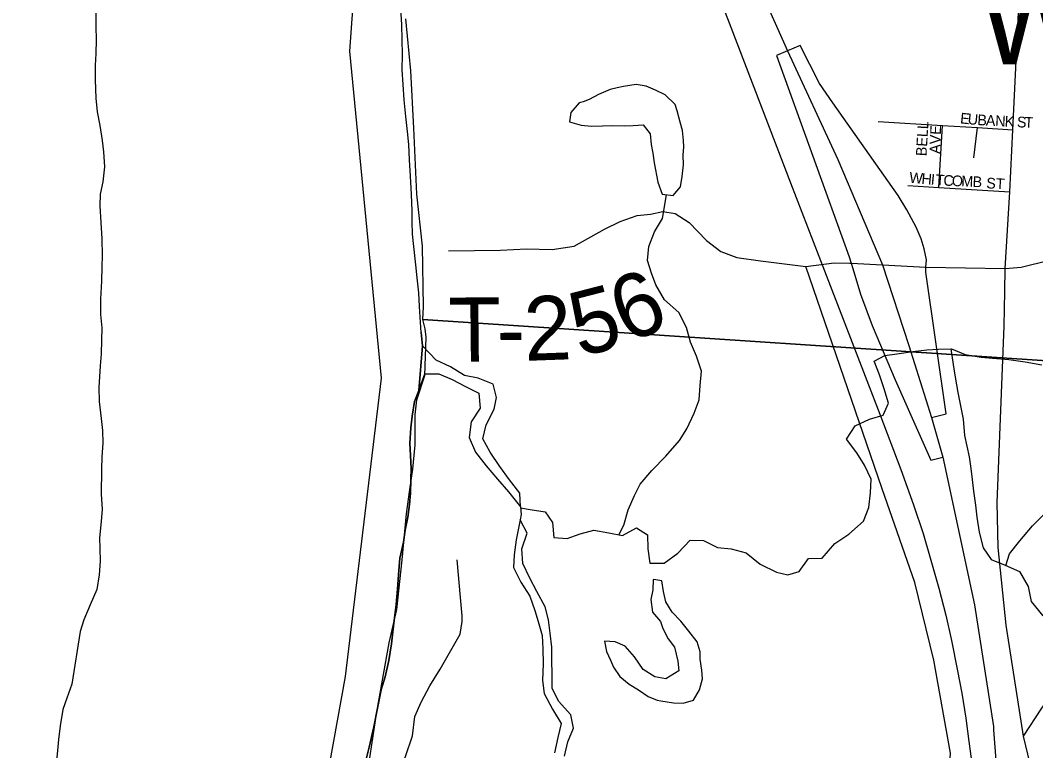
# Model space of a CAD drawing. Extents: x 1624196 to 2029251, y 146837 to 440034.
# Drawn here: x 1861259 to 1866006, y 263439 to 266854 of the extents above; entities that cross this region are included whole.
import ezdxf

# ---------------------------------------------------------------- set-up
doc = ezdxf.new("R2010")
doc.units = 0
for name, color, linetype in [('GM_X_County', 7, 'Continuous'), ('GM_X_County_Road', 7, 'Continuous'), ('GM_X_Interchange_Ramps', 7, 'Continuous'), ('GM_X_Major_River', 7, 'Continuous'), ('GM_X_Minor_Lake', 7, 'Continuous'), ('GM_X_Minor_River', 7, 'Continuous'), ('GM_X_Rail_Line', 7, 'Continuous'), ('GM_X_Section', 7, 'Continuous'), ('GM_X_Township', 7, 'Continuous'), ('GM_X_Township_Road', 7, 'Continuous'), ('GM_X_Township_Road_Text', 7, 'Continuous'), ('GM_X_Township_Subdivision', 7, 'Continuous'), ('GM_X_Township_Subdivision_Text', 7, 'Continuous'), ('GM_X_Unincorporated_Text', 7, 'Continuous'), ('GM_X_US_Route', 7, 'Continuous')]:
    doc.layers.add(name, color=color, linetype=linetype)

msp = doc.modelspace()

# ---------------------------------------------------------------- linework, layer by layer
at = {"layer": 'GM_X_County'}
msp.add_lwpolyline([(1861843.4, 259153), (1862035.4, 260236.2), (1862367.4, 261505.6), (1862779.4, 263786.1), (1862947.5, 265181.7), (1862799.4, 266709.4), (1862843.4, 267316), (1862763.4, 267754.5), (1862639.3, 268445.3), (1862487.3, 269170.1), (1861981.2, 270988.1)], dxfattribs=at)
at = {"layer": 'GM_X_County_Road'}
for points in [[(1865863.4, 265693.9), (1865885.2, 266051.4), (1865900.3, 266342.6), (1865929.5, 266955.7), (1865926.1, 266996.5), (1865898.2, 267331), (1865896.1, 267346.9), (1865864.8, 267587.2), (1865804.2, 267809), (1865652.5, 268167.6), (1865418.2, 268553.8), (1865101.1, 268983.1), (1864229.9, 270238.6), (1863859.8, 270764.2), (1863654.2, 271050.8), (1863523.3, 271223.8), (1863423.3, 271348.3)], [(1865950, 263507.3), (1866034.8, 263637.4), (1866288, 263981.4), (1866419, 264182.9), (1866423.7, 264340), (1866465.6, 265074.8), (1866481.8, 265246.8), (1866507.6, 265556.1), (1866547.4, 266035.5), (1866595.6, 266755), (1866622.7, 266795.6)], [(1865863.4, 265693.9), (1865938.4, 265700.3), (1866071.1, 265732), (1866071.3, 265732.2)], [(1864931.8, 265703.2), (1865063.4, 265720.6), (1865138, 265719.1)], [(1865418.7, 262834.6), (1865578.9, 263041.4), (1865602.6, 263332.1), (1865608.2, 263428.2), (1865530.6, 263862.9), (1865441.2, 264225.9), (1865288.3, 264663.7), (1864931.8, 265703.2)], [(1865138, 265719.1), (1865144, 265719), (1865289.4, 265711.1), (1865493.1, 265700), (1865863.4, 265693.9)], [(1865861.6, 265586.7), (1865863.4, 265693.9)], [(1867016.2, 259449.3), (1866680.5, 260648), (1866378.1, 261727.9), (1865950, 263507.3), (1865868, 264025.5), (1865831.5, 264390), (1865827, 264599.6), (1865858.9, 265423.9), (1865861.6, 265586.7)]]:
    msp.add_lwpolyline(points, dxfattribs=at)
at = {"layer": 'GM_X_Interchange_Ramps'}
for points in [[(1865493.1, 265700), (1865496, 265735), (1865484.2, 265786), (1865470.9, 265832.2), (1865447.8, 265886.8), (1865404, 265968.5), (1865362.9, 266035.5), (1865057.9, 266468.9), (1864996.3, 266558.4), (1864905.3, 266736.4), (1864846, 266712.1)], [(1864846, 266712.1), (1864794.2, 266689.2), (1865133.9, 265747.6), (1865144, 265719)], [(1865144, 265719), (1865150.7, 265693), (1865187.7, 265574.1), (1865241.6, 265426.8), (1865349.6, 265173.5), (1865466.1, 264910), (1865516.5, 264797.1), (1865572, 264811.4)], [(1865519, 264997.2), (1865587.5, 265014.8), (1865493.5, 265677.2), (1865493.1, 265700)]]:
    msp.add_lwpolyline(points, dxfattribs=at)
at = {"layer": 'GM_X_Major_River'}
for p, q in [((1863138.6, 265331.8), (1863132.9, 265393.9)), ((1863138.6, 265331.8), (1863121.5, 265123.5)), ((1863121.5, 265123.5), (1863138.6, 265331.8))]:
    msp.add_line(p, q, dxfattribs=at)
for points in [[(1861612.7, 266890.6), (1861612.4, 266824.5), (1861614, 266762.4), (1861611.7, 266698.3), (1861609.4, 266642.3), (1861609.1, 266576.2), (1861612.7, 266490), (1861618.4, 266425.9), (1861630, 266361.8), (1861641.7, 266291.6), (1861647.4, 266239.5), (1861653.1, 266169.4), (1861644.7, 266099.3), (1861632.4, 266041.3), (1861630.2, 265987.2), (1861635.8, 265909.1), (1861639.4, 265833), (1861641, 265754.9), (1861640.7, 265700.8), (1861638.4, 265634.7), (1861634, 265550.6), (1861633.6, 265478.5), (1861639.3, 265416.4), (1861639, 265358.3), (1861636.7, 265294.2), (1861632.4, 265238.2), (1861625.9, 265138), (1861627.6, 265072), (1861637.2, 264991.8), (1861642.9, 264935.7), (1861644.6, 264877.6), (1861640.3, 264813.5), (1861638, 264755.5), (1861637.5, 264639.3), (1861641.1, 264569.2), (1861636.8, 264511.1), (1861628.4, 264435), (1861630.2, 264385), (1861631.9, 264324.9), (1861627.6, 264260.8), (1861617.2, 264192.7), (1861584.9, 264120.8), (1861556.5, 264050.8), (1861538.3, 263996.8), (1861500.5, 263750.6)], [(1863132.9, 265393.9), (1863129.2, 265466), (1863125.5, 265516.1), (1863121.8, 265580.2), (1863114.2, 265650.3), (1863108.5, 265710.4), (1863098.9, 265796.6), (1863093.2, 265854.7), (1863091.5, 265912.8), (1863091.7, 265962.8), (1863088.1, 266039), (1863082.5, 266125.1), (1863078.9, 266201.2), (1863075.3, 266273.4), (1863069.6, 266333.5), (1863061.9, 266403.6), (1863054.3, 266481.8), (1863048.7, 266553.9), (1863045, 266622), (1863045.4, 266694.1), (1863043.7, 266762.2), (1863042.1, 266834.3), (1863038.5, 266908.4)], [(1863132.9, 265393.9), (1863138.6, 265331.8)], [(1862877.1, 263406.1), (1862889.3, 263456.2), (1862911.8, 263550.2), (1862928.2, 263638.2), (1862946.6, 263724.3), (1862964.9, 263784.3), (1862981.3, 263860.3), (1862993.7, 263938.4), (1862999.9, 263994.4), (1863008.3, 264060.5), (1863016.6, 264122.6), (1863022.9, 264194.6), (1863027.3, 264260.7), (1863033.7, 264338.8), (1863050, 264414.8), (1863058.3, 264470.9), (1863070.6, 264530.9), (1863078.9, 264591), (1863083.2, 264643), (1863085.5, 264707.1), (1863085.7, 264759.2), (1863084, 264819.2), (1863080.3, 264877.3), (1863084.7, 264949.4), (1863091, 265003.5), (1863101.3, 265071.5), (1863121.5, 265123.5)], [(1863121.5, 265123.5), (1863101.3, 265071.5), (1863091, 265003.5), (1863084.7, 264949.4), (1863080.3, 264877.3), (1863084, 264819.2), (1863085.7, 264759.2), (1863085.5, 264707.1), (1863083.2, 264643), (1863078.9, 264591), (1863070.6, 264530.9), (1863058.3, 264470.9), (1863050, 264414.8), (1863033.7, 264338.8), (1863027.3, 264260.7), (1863022.9, 264194.6), (1863016.6, 264122.6), (1863008.3, 264060.5), (1862999.9, 263994.4), (1862993.7, 263938.4), (1862981.3, 263860.3), (1862964.9, 263784.3), (1862946.6, 263724.3), (1862928.2, 263638.2), (1862911.8, 263550.2), (1862889.3, 263456.2), (1862877.1, 263406.1)], [(1861500.5, 263750.6), (1861476.2, 263684.4), (1861457.9, 263632.3), (1861445.6, 263556.1), (1861437.3, 263491.9), (1861431, 263423.7), (1861422.7, 263357.4), (1861412.4, 263279.2), (1861404.1, 263221), (1861399.8, 263138.7), (1861395.5, 263070.5), (1861391.2, 263008.2), (1861382.9, 262940), (1861378.7, 262883.8), (1861372.4, 262815.5), (1861363.9, 262715.2), (1861353.6, 262643), (1861341.3, 262584.8), (1861329.1, 262520.6), (1861314.8, 262456.5), (1861296.4, 262388.3), (1861284.2, 262326.1), (1861267.9, 262255.9), (1861258.8, 262210.4)], [(1861500.5, 263750.6), (1861476.2, 263684.4), (1861457.9, 263632.3), (1861445.6, 263556.1), (1861437.3, 263491.9), (1861431, 263423.7)]]:
    msp.add_lwpolyline(points, dxfattribs=at)
at = {"layer": 'GM_X_Minor_Lake'}
for points in [[(1864259.5, 266040.7), (1864311.4, 266034.3), (1864345.6, 266076.2), (1864353.9, 266124.1), (1864360.3, 266178.2), (1864358.6, 266224.2), (1864360.8, 266262.2), (1864359, 266292.3), (1864355.3, 266338.3), (1864343.6, 266378.4), (1864329.9, 266430.6), (1864320.1, 266460.7), (1864274.4, 266505), (1864228.6, 266527.3), (1864184.7, 266545.6), (1864138.8, 266553.9), (1864078.8, 266544.2), (1864048.8, 266538.4), (1864016.8, 266530.6), (1863962.7, 266507), (1863918.6, 266483.2), (1863890.5, 266473.6)], [(1863890.5, 266473.6), (1863872.5, 266467.5), (1863832.3, 266423.7), (1863826, 266379.7), (1863881.8, 266363.3), (1863929.8, 266359), (1863981.7, 266360.7), (1864029.7, 266362.4), (1864081.7, 266360.1), (1864123.6, 266361.8), (1864171.6, 266365.5), (1864203.3, 266323.3), (1864209, 266273.2), (1864216.7, 266233.1), (1864222.5, 266187), (1864239.9, 266096.8), (1864259.5, 266040.7)], [(1864230.1, 264237.5), (1864218.2, 264239.4), (1864215.9, 264191.4), (1864207.6, 264145.4), (1864215.2, 264087.3), (1864252.9, 264043), (1864262.7, 264010.9), (1864288.4, 263962.7), (1864318.1, 263922.5), (1864333.7, 263858.3), (1864337.4, 263812.3), (1864277.2, 263774.6), (1864225.3, 263785), (1864171.6, 263819.3), (1864130, 263877.6), (1864086.3, 263928), (1864040.5, 263948.3), (1863990.6, 263950.6), (1864000.2, 263902.5), (1864018, 263862.3), (1864031.8, 263830.2), (1864061.5, 263786), (1864105.2, 263749.7), (1864149, 263723.4), (1864194.8, 263693.1), (1864236.6, 263674.8), (1864253.8, 263672.6)], [(1864253.8, 263672.6), (1864312.5, 263662.3), (1864358.4, 263662), (1864406.5, 263675.7), (1864434.8, 263723.6), (1864449.1, 263775.5), (1864445.3, 263815.6), (1864437.7, 263867.7), (1864437.9, 263901.7), (1864424.2, 263947.8), (1864384.5, 263998.1), (1864346.8, 264044.4), (1864307.1, 264086.7), (1864277.5, 264134.9), (1864265.8, 264183), (1864258.1, 264233.1), (1864230.1, 264237.5)]]:
    msp.add_lwpolyline(points, dxfattribs=at)
at = {"layer": 'GM_X_Minor_River'}
msp.add_line((1863138.6, 265331.8), (1863121.5, 265123.5), dxfattribs=at)
for points in [[(1864058, 264448.5), (1864080.1, 264493.4), (1864100.7, 264565.3), (1864131.2, 264633.1), (1864157.6, 264685), (1864212.1, 264748.6), (1864276.5, 264816.2), (1864341.1, 264889.8), (1864375.5, 264943.5), (1864410, 265017.3), (1864432.5, 265079.2), (1864437, 265147.3), (1864443.6, 265213.3), (1864420.1, 265283.6), (1864392.7, 265349.8), (1864373.2, 265418.1), (1864337.8, 265488.4), (1864270.3, 265547), (1864230.9, 265617.4), (1864209.3, 265671.6), (1864191.8, 265731.8), (1864198.3, 265795.9), (1864224.8, 265865.7), (1864261.3, 265927.5), (1864279.5, 266038.2)], [(1863121.5, 265123.5), (1863150.4, 265201.4), (1863216.3, 265200.9), (1863278.1, 265174.4), (1863339.8, 265141.9), (1863403.5, 265111.4), (1863408.9, 265041.2), (1863366.5, 264977.5), (1863357.9, 264903.5), (1863387.3, 264835.2), (1863436.8, 264770.7), (1863490.2, 264708.2), (1863541.8, 264649.8), (1863597.2, 264579.2), (1863593.7, 264643.3), (1863546.2, 264705.8), (1863500.7, 264768.2), (1863455.3, 264834.6), (1863421.8, 264897), (1863436.3, 264962.9), (1863474.8, 265036.7), (1863485.3, 265090.7), (1863469.8, 265152.9), (1863400, 265181.5), (1863336.2, 265194), (1863270.5, 265234.5), (1863202.8, 265265.1), (1863138.6, 265331.8)], [(1863597.6, 264575), (1863643, 264566.9), (1863712.9, 264556.3), (1863746.5, 264506), (1863753.9, 264435.9), (1863815.8, 264431.4), (1863876, 264452.9), (1863940.1, 264470.4), (1864009.9, 264457.9), (1864073.8, 264445.4), (1864140, 264480.9), (1864191.7, 264448.4), (1864193.2, 264382.3), (1864202.7, 264316.2), (1864268.6, 264315.7), (1864332.9, 264363.2), (1864391.4, 264422.8), (1864453.3, 264422.4), (1864519, 264389.8), (1864582.9, 264383.3), (1864652.7, 264364.7), (1864718.3, 264312.1), (1864793.9, 264273.5), (1864847.8, 264261.1), (1864899.8, 264276.7), (1864944.3, 264338.4), (1865008.3, 264339.9), (1865066.8, 264407.5), (1865133, 264451), (1865201.5, 264512.6), (1865226, 264576.5), (1865234.5, 264644.5), (1865237, 264708.5), (1865205.6, 264774.8), (1865170, 264831.2), (1865122.6, 264895.6), (1865163, 264957.4), (1865229.2, 264988.9), (1865293.3, 265008.4), (1865317.8, 265064.3), (1865298.3, 265130.5), (1865276.8, 265196.7), (1865251.4, 265261), (1865301.5, 265286.6), (1865357.5, 265294.2), (1865431.6, 265305.6), (1865497.6, 265313.1), (1865551.6, 265316.7), (1865613.5, 265318.2), (1865677.3, 265291.7), (1865751.1, 265279.1), (1865805.1, 265274.7), (1865881, 265268.1), (1865956.8, 265257.5), (1866034.7, 265242.8)], [(1865609.4, 265318.1), (1865621, 265244.1), (1865630.5, 265186), (1865641.9, 265113.8), (1865653.5, 265059.6), (1865666.9, 264989.5), (1865674.3, 264913.3), (1865683.9, 264863.2), (1865695.5, 264813), (1865703.1, 264758.9), (1865708.7, 264706.8), (1865716.2, 264652.7), (1865725.7, 264586.5), (1865731.3, 264530.4), (1865742.7, 264460.3), (1865760.1, 264388), (1865797.7, 264333.7), (1865863.4, 264307.2), (1865931.1, 264276.6), (1865970.5, 264206.2), (1865986, 264136), (1866039.4, 264069.5)], [(1863597.2, 264579.2), (1863600.8, 264543.6), (1863596.7, 264519.2)], [(1865866.9, 264305.6), (1865883.8, 264359), (1865932.2, 264420.7), (1865990.8, 264490.4), (1866051.2, 264549.9)], [(1863596.7, 264519.2), (1863578, 264425.2), (1863567.4, 264355.2), (1863564.9, 264295.2), (1863598.4, 264226.9), (1863641.8, 264162.4), (1863665.3, 264094.2), (1863680.9, 264044), (1863698.3, 263977.8), (1863701.9, 263915.7), (1863703.3, 263845.6), (1863700.7, 263767.5), (1863708.2, 263707.4), (1863747.6, 263633), (1863787, 263566.6), (1863772.5, 263500.7), (1863756, 263428.7)], [(1863803.8, 263414.3), (1863818.3, 263480.3), (1863844.8, 263544.2), (1863833.3, 263606.3), (1863775.9, 263670.8), (1863746.4, 263731.1), (1863744.9, 263799.2), (1863743.4, 263859.3), (1863743.9, 263923.4), (1863736.4, 263989.5), (1863728.9, 264051.6), (1863713.4, 264111.8), (1863674, 264184.2), (1863640.5, 264246.5), (1863609.1, 264314.9), (1863603.6, 264383), (1863628.2, 264456.9), (1863596.7, 264519.2)]]:
    msp.add_lwpolyline(points, dxfattribs=at)
at = {"layer": 'GM_X_Rail_Line'}
msp.add_lwpolyline([(1864240.5, 267704.5), (1864580.6, 266822.7), (1864859.5, 266094.9), (1865045.7, 265614.5), (1865277, 265012.4), (1865375.4, 264753.7), (1865435.8, 264588.4), (1865480.1, 264454.6), (1865513.2, 264340.2), (1865554.3, 264199.1), (1865585.7, 264072.6), (1865613.1, 263954.1), (1865640.5, 263813.1), (1865661.5, 263707.5), (1865679.2, 263591.4), (1865694.5, 263482.6), (1865705, 263402.8)], dxfattribs=at)
at = {"layer": 'GM_X_Section'}
for points in [[(1866483.9, 265233.4), (1863140.4, 265454.9), (1863144.6, 265514.9), (1863139.6, 265798.9), (1863112.4, 266041), (1863099.5, 266349.1), (1863084.4, 266617.2), (1863061.2, 266861.3)], [(1862893.4, 263405.5), (1862926.1, 263621.5), (1862983.2, 263943.3), (1863019.8, 264099.2), (1863044.6, 264331.1), (1863065.3, 264547.1), (1863079.7, 264661), (1863094, 264755), (1863104.4, 264868.9), (1863104.9, 265009), (1863113.1, 265078.9), (1863149.5, 265192.9), (1863156.1, 265372.8), (1863152.3, 265410.9), (1863140.4, 265454.9), (1866483.9, 265233.4)]]:
    msp.add_lwpolyline(points, dxfattribs=at)
at = {"layer": 'GM_X_Township'}
msp.add_lwpolyline([(1861843.4, 259153), (1862035.4, 260236.2), (1862367.4, 261505.6), (1862779.4, 263786.1), (1862947.5, 265181.7), (1862799.4, 266709.4), (1862843.4, 267316), (1862763.4, 267754.5), (1862639.3, 268445.3), (1862487.3, 269170.1), (1861981.2, 270988.1)], dxfattribs=at)
at = {"layer": 'GM_X_Township_Road'}
msp.add_lwpolyline([(1863260.3, 265776.7), (1863503.3, 265779.3), (1863626.1, 265785.7), (1863746.3, 265781.9), (1863848.9, 265798.9), (1863989.9, 265877.9), (1864063.8, 265913.1), (1864142.7, 265941.7), (1864204.8, 265948.4), (1864263.6, 265960.2), (1864320.6, 265950.1), (1864386.1, 265908.1), (1864466.7, 265824.1), (1864533.9, 265773.7), (1864609.4, 265745.2), (1864720.2, 265730), (1864931.8, 265703.2)], dxfattribs=at)
at = {"layer": 'GM_X_Township_Subdivision'}
for points in [[(1865269.8, 266381.1), (1865570.2, 266362.8), (1865734.1, 266352.7), (1865900.3, 266342.6)], [(1865553, 266072.7), (1865570.2, 266362.8)], [(1865717.9, 266211.5), (1865734.1, 266352.7)], [(1865408.4, 266081.9), (1865553, 266072.7), (1865885.2, 266051.4)], [(1862759.7, 261531.3), (1862760.1, 261533.9), (1862874.4, 262276.5), (1862887.1, 262382.5), (1862907.6, 262462.5), (1862904.3, 262574.6), (1862883.5, 262749), (1862878.1, 262833.2), (1862886.7, 262925.2), (1862903.4, 263029.2), (1862934.2, 263149.1), (1863059.7, 263412.6), (1863092.3, 263508.4), (1863102.9, 263598.5), (1863133.3, 263666.3), (1863173.7, 263742.2), (1863222.2, 263819.9), (1863315.1, 263983.4), (1863324.9, 264042.5), (1863324.9, 264069.8), (1863316.3, 264155.6), (1863301.1, 264330.9)]]:
    msp.add_lwpolyline(points, dxfattribs=at)
at = {"layer": 'GM_X_US_Route'}
msp.add_lwpolyline([(1864103.9, 268821), (1864164.1, 268630.5), (1864375.7, 267882), (1864554.7, 267366.1), (1864846, 266712.1), (1865081.9, 266202.9), (1865289.4, 265711.1), (1865413, 265333.7), (1865519, 264997.2), (1865572, 264811.4), (1865719.8, 264121.8), (1865808.4, 263552.3), (1865809.6, 263536.7), (1865825.6, 263314.4)], dxfattribs=at)

# ---------------------------------------------------------------- texts
at = {"layer": 'GM_X_Township_Road_Text'}
for s, rotation, p in [('6', 23.0909, (1864098.1, 265340.4)), ('5', 14.4769, (1863872.7, 265278.4)), ('T', 0.5786, (1863262, 265257.3)), ('2', 2.0572, (1863618, 265261.6)), ('-', 0.8176, (1863487.7, 265259.6))]:
    msp.add_text(s, height=300, rotation=rotation, dxfattribs=at).set_placement(p)
at = {"layer": 'GM_X_Township_Subdivision_Text'}
for s, rotation, p in [('E', 354.0475, (1865651.4, 266372.6)), ('U', 354.3669, (1865686.7, 266368.9)), ('B', 356.4032, (1865732.4, 266364.5)), ('A', 357.0541, (1865772.5, 266361.9)), ('N', 357.0881, (1865816.5, 266359.7)), ('K', 357.0936, (1865860.5, 266357.4)), ('S', 357.0885, (1865917.6, 266354.5)), ('T', 357.0872, (1865952.8, 266352.7)), ('BELL', 86.6354, (1865495.8, 266217.8)), ('AVE', 88.0261, (1865559.7, 266229.1)), ('W', 354.6792, (1865413.7, 266095.4)), ('H', 354.67, (1865470.6, 266090.1)), ('I', 354.692, (1865514.4, 266086)), ('T', 356.1083, (1865537.7, 266083.9)), ('C', 357.3793, (1865574, 266081.4)), ('O', 357.4652, (1865613.6, 266079.6)), ('M', 357.4495, (1865657.6, 266077.6)), ('B', 357.463, (1865710.4, 266075.3)), ('ST', 356.4186, (1865774.1, 266069))]:
    msp.add_text(s, height=50, rotation=rotation, dxfattribs=at).set_placement(p)
at = {"layer": 'GM_X_Unincorporated_Text'}
msp.add_text('Wheelersburg', height=417, rotation=0, dxfattribs=at).set_placement((1865738.4, 266649))

doc.saveas('drawing.dxf')
